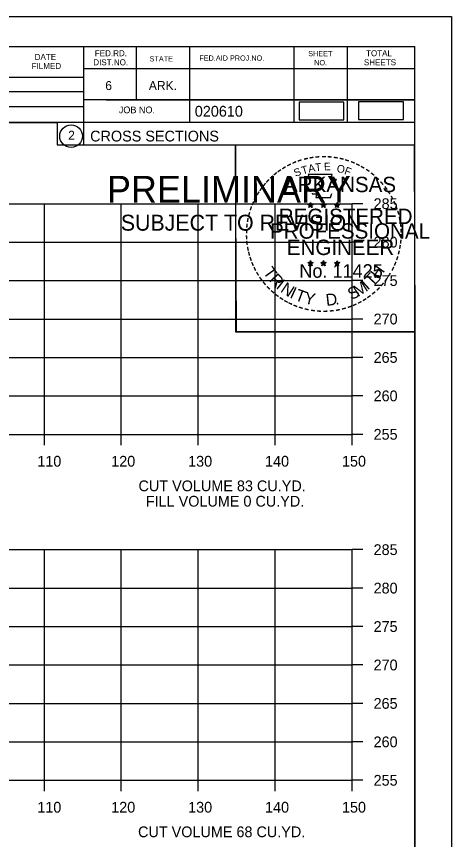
# Model space of a CAD drawing. Extents: x 1103485 to 1107180, y 2010593 to 2011873.
# Drawn here: x 1107123.6 to 1107180.1, y 2010699.1 to 2010806.2 of the extents above; entities that cross this region are included whole.
import ezdxf

# ---------------------------------------------------------------- set-up
doc = ezdxf.new("R2010")
doc.units = 0
for name, color, linetype in [('R_Axis', 7, 'Continuous'), ('R_Axis Annot', 7, 'Continuous'), ('R_Border', 7, 'Continuous'), ('R_Border PE', 7, 'Continuous'), ('R_Border Prem', 7, 'Continuous'), ('R_Grid', 7, 'Continuous'), ('R_No Plot', 7, 'Continuous'), ('R_Water', 7, 'Continuous')]:
    doc.layers.add(name, color=color, linetype=linetype)

msp = doc.modelspace()

# ---------------------------------------------------------------- linework, layer by layer
at = {"layer": 'R_Axis'}
for p, q in [((1107167.18, 2010751.82), (1107167.18, 2010781.82)), ((1107168.58, 2010781.82), (1107167.18, 2010781.82)), ((1107168.58, 2010776.82), (1107167.18, 2010776.82)), ((1107168.58, 2010771.82), (1107167.18, 2010771.82)), ((1107168.58, 2010766.82), (1107167.18, 2010766.82)), ((1107168.58, 2010761.82), (1107167.18, 2010761.82)), ((1107168.58, 2010756.82), (1107167.18, 2010756.82)), ((1106867.18, 2010751.82), (1107167.18, 2010751.82)), ((1107127.18, 2010750.42), (1107127.18, 2010751.82)), ((1107137.18, 2010750.42), (1107137.18, 2010751.82)), ((1107147.18, 2010750.42), (1107147.18, 2010751.82)), ((1107157.18, 2010750.42), (1107157.18, 2010751.82)), ((1107167.18, 2010750.42), (1107167.18, 2010751.82)), ((1107168.58, 2010751.82), (1107167.18, 2010751.82)), ((1107167.18, 2010706.82), (1107167.18, 2010736.82)), ((1107168.58, 2010736.82), (1107167.18, 2010736.82)), ((1107168.58, 2010731.82), (1107167.18, 2010731.82)), ((1107168.58, 2010726.82), (1107167.18, 2010726.82)), ((1107168.58, 2010721.82), (1107167.18, 2010721.82)), ((1107168.58, 2010716.82), (1107167.18, 2010716.82)), ((1107168.58, 2010711.82), (1107167.18, 2010711.82)), ((1106867.18, 2010706.82), (1107167.18, 2010706.82)), ((1107127.18, 2010705.42), (1107127.18, 2010706.82)), ((1107137.18, 2010705.42), (1107137.18, 2010706.82)), ((1107147.18, 2010705.42), (1107147.18, 2010706.82)), ((1107157.18, 2010705.42), (1107157.18, 2010706.82)), ((1107167.18, 2010705.42), (1107167.18, 2010706.82)), ((1107168.58, 2010706.82), (1107167.18, 2010706.82))]:
    msp.add_line(p, q, dxfattribs=at)
at = {"layer": 'R_Border'}
for p, q in [((1106859.18, 2010802.28), (1107175.36, 2010802.28)), ((1107132.26, 2010802.28), (1107132.26, 2010789.48)), ((1107139.1, 2010802.28), (1107139.1, 2010795.34)), ((1107146.04, 2010802.28), (1107146.04, 2010792.4)), ((1107159.62, 2010802.28), (1107159.62, 2010792.4)), ((1107166.56, 2010802.28), (1107166.56, 2010792.4)), ((1107175.36, 2010596.82), (1107175.36, 2010802.28)), ((1107175.36, 2010799.34), (1107132.26, 2010799.34)), ((1107175.36, 2010799.36), (1107175.36, 2010799.36)), ((1107093.1, 2010798.26), (1107132.26, 2010798.26)), ((1107093.1, 2010796.4), (1107132.26, 2010796.4)), ((1107175.36, 2010795.34), (1107132.26, 2010795.34)), ((1107135.22, 2010795.34), (1107175.36, 2010795.34)), ((1107093.1, 2010794.46), (1107132.26, 2010794.46)), ((1107175.36, 2010792.4), (1107093.1, 2010792.4)), ((1107132.26, 2010789.48), (1107175.36, 2010789.48))]:
    msp.add_line(p, q, dxfattribs=at)
msp.add_circle((1107130.65, 2010790.61), 1.47, dxfattribs=at)
at = {"layer": 'R_Border PE'}
for p, q in [((1107161.45, 2010781.73), (1107161.8, 2010781.62)), ((1107161.45, 2010781.73), (1107161.7, 2010781.69)), ((1107161.45, 2010781.73), (1107161.69, 2010781.61)), ((1107161.58, 2010781.32), (1107161.8, 2010781.62)), ((1107161.58, 2010781.32), (1107161.71, 2010781.57)), ((1107161.58, 2010781.32), (1107161.8, 2010781.54)), ((1107161.8, 2010781.99), (1107161.76, 2010781.73)), ((1107161.8, 2010781.62), (1107161.8, 2010781.99)), ((1107161.8, 2010781.99), (1107161.85, 2010781.74)), ((1107162.14, 2010781.73), (1107161.8, 2010781.62)), ((1107162.01, 2010781.32), (1107161.8, 2010781.62)), ((1107162.01, 2010781.32), (1107161.8, 2010781.54)), ((1107162.14, 2010781.73), (1107161.86, 2010781.68)), ((1107162.01, 2010781.32), (1107161.87, 2010781.61)), ((1107162.14, 2010781.73), (1107161.94, 2010781.63)), ((1107163.12, 2010781.73), (1107163.47, 2010781.62)), ((1107163.12, 2010781.73), (1107163.37, 2010781.69)), ((1107163.12, 2010781.73), (1107163.36, 2010781.61)), ((1107163.25, 2010781.32), (1107163.47, 2010781.62)), ((1107163.25, 2010781.32), (1107163.38, 2010781.57)), ((1107163.25, 2010781.32), (1107163.47, 2010781.54)), ((1107163.47, 2010781.99), (1107163.43, 2010781.73)), ((1107163.47, 2010781.62), (1107163.47, 2010781.99)), ((1107163.47, 2010781.99), (1107163.52, 2010781.74)), ((1107163.81, 2010781.73), (1107163.47, 2010781.62)), ((1107163.68, 2010781.32), (1107163.47, 2010781.62)), ((1107163.68, 2010781.32), (1107163.47, 2010781.54)), ((1107163.81, 2010781.73), (1107163.53, 2010781.68)), ((1107163.68, 2010781.32), (1107163.54, 2010781.61)), ((1107163.81, 2010781.73), (1107163.61, 2010781.63)), ((1107164.88, 2010781.72), (1107165.23, 2010781.61)), ((1107164.88, 2010781.72), (1107165.14, 2010781.67)), ((1107164.88, 2010781.72), (1107165.12, 2010781.6)), ((1107165.02, 2010781.31), (1107165.23, 2010781.61)), ((1107165.02, 2010781.31), (1107165.14, 2010781.56)), ((1107165.02, 2010781.31), (1107165.23, 2010781.53)), ((1107165.23, 2010781.97), (1107165.19, 2010781.72)), ((1107165.23, 2010781.61), (1107165.23, 2010781.97)), ((1107165.23, 2010781.97), (1107165.28, 2010781.72)), ((1107165.58, 2010781.72), (1107165.23, 2010781.61)), ((1107165.44, 2010781.31), (1107165.23, 2010781.61)), ((1107165.44, 2010781.31), (1107165.23, 2010781.53)), ((1107165.58, 2010781.72), (1107165.29, 2010781.67)), ((1107165.44, 2010781.31), (1107165.31, 2010781.6)), ((1107165.58, 2010781.72), (1107165.37, 2010781.62)), ((1107161.44, 2010774.16), (1107161.79, 2010774.05)), ((1107161.44, 2010774.16), (1107161.7, 2010774.11)), ((1107161.44, 2010774.16), (1107161.68, 2010774.04)), ((1107161.58, 2010773.75), (1107161.79, 2010774.05)), ((1107161.58, 2010773.75), (1107161.7, 2010773.99)), ((1107161.58, 2010773.75), (1107161.79, 2010773.97)), ((1107161.79, 2010774.41), (1107161.75, 2010774.16)), ((1107161.79, 2010774.05), (1107161.79, 2010774.41)), ((1107161.79, 2010774.41), (1107161.84, 2010774.16)), ((1107162.14, 2010774.16), (1107161.79, 2010774.05)), ((1107162.01, 2010773.75), (1107161.79, 2010774.05)), ((1107162.01, 2010773.75), (1107161.79, 2010773.96)), ((1107162.14, 2010774.16), (1107161.85, 2010774.11)), ((1107162.01, 2010773.75), (1107161.87, 2010774.04)), ((1107162.14, 2010774.16), (1107161.94, 2010774.06)), ((1107163.11, 2010774.16), (1107163.46, 2010774.05)), ((1107163.11, 2010774.16), (1107163.37, 2010774.11)), ((1107163.11, 2010774.16), (1107163.35, 2010774.04)), ((1107163.25, 2010773.75), (1107163.46, 2010774.05)), ((1107163.25, 2010773.75), (1107163.37, 2010773.99)), ((1107163.25, 2010773.75), (1107163.46, 2010773.97)), ((1107163.46, 2010774.41), (1107163.42, 2010774.16)), ((1107163.46, 2010774.05), (1107163.46, 2010774.41)), ((1107163.46, 2010774.41), (1107163.51, 2010774.16)), ((1107163.81, 2010774.16), (1107163.46, 2010774.05)), ((1107163.68, 2010773.75), (1107163.46, 2010774.05)), ((1107163.68, 2010773.75), (1107163.46, 2010773.96)), ((1107163.81, 2010774.16), (1107163.52, 2010774.11)), ((1107163.68, 2010773.75), (1107163.54, 2010774.04)), ((1107163.81, 2010774.16), (1107163.61, 2010774.06)), ((1107164.88, 2010774.15), (1107165.23, 2010774.04)), ((1107164.88, 2010774.15), (1107165.13, 2010774.1)), ((1107164.88, 2010774.15), (1107165.12, 2010774.03)), ((1107165.01, 2010773.74), (1107165.23, 2010774.04)), ((1107165.01, 2010773.74), (1107165.14, 2010773.98)), ((1107165.01, 2010773.74), (1107165.23, 2010773.96)), ((1107165.23, 2010774.4), (1107165.19, 2010774.15)), ((1107165.23, 2010774.04), (1107165.23, 2010774.4)), ((1107165.23, 2010774.4), (1107165.28, 2010774.15)), ((1107165.58, 2010774.15), (1107165.23, 2010774.04)), ((1107165.44, 2010773.74), (1107165.23, 2010774.04)), ((1107165.44, 2010773.74), (1107165.23, 2010773.95)), ((1107165.58, 2010774.15), (1107165.29, 2010774.1)), ((1107165.44, 2010773.74), (1107165.31, 2010774.03)), ((1107165.58, 2010774.15), (1107165.37, 2010774.05))]:
    msp.add_line(p, q, dxfattribs=at)
for points in [[(1107161.49, 2010785.61), (1107161.76, 2010784.78)], [(1107165, 2010784.69), (1107165.14, 2010784.97), (1107164.46, 2010784.95), (1107164.61, 2010785.61), (1107161.49, 2010785.61)], [(1107161.98, 2010783.19), (1107161.98, 2010783.1), (1107162.54, 2010783.08), (1107162.49, 2010782.61), (1107164.36, 2010782.61), (1107164.56, 2010783.14)], [(1107161.8, 2010781.99), (1107162.01, 2010781.32), (1107161.45, 2010781.73), (1107162.14, 2010781.73), (1107161.58, 2010781.32), (1107161.8, 2010781.99)], [(1107163.47, 2010781.99), (1107163.68, 2010781.32), (1107163.12, 2010781.73), (1107163.81, 2010781.73), (1107163.25, 2010781.32), (1107163.47, 2010781.99)], [(1107165.23, 2010781.97), (1107165.44, 2010781.31), (1107164.88, 2010781.72), (1107165.58, 2010781.72), (1107165.02, 2010781.31), (1107165.23, 2010781.97)], [(1107161.79, 2010774.41), (1107162.01, 2010773.75), (1107161.44, 2010774.16), (1107162.14, 2010774.16), (1107161.58, 2010773.75), (1107161.79, 2010774.41)], [(1107163.46, 2010774.41), (1107163.68, 2010773.75), (1107163.11, 2010774.16), (1107163.81, 2010774.16), (1107163.25, 2010773.75), (1107163.46, 2010774.41)], [(1107165.23, 2010774.4), (1107165.44, 2010773.74), (1107164.88, 2010774.15), (1107165.58, 2010774.15), (1107165.01, 2010773.74), (1107165.23, 2010774.4)]]:
    msp.add_lwpolyline(points, dxfattribs=at)
for centre, radius in [((1107161.8, 2010781.62), 0.172), ((1107161.8, 2010781.62), 0.145), ((1107161.8, 2010781.62), 0.116), ((1107161.8, 2010781.62), 0.0991), ((1107161.8, 2010781.62), 0.0747), ((1107161.8, 2010781.62), 0.0495), ((1107161.8, 2010781.62), 0.0296), ((1107163.47, 2010781.62), 0.172), ((1107163.47, 2010781.62), 0.145), ((1107163.47, 2010781.62), 0.116), ((1107163.47, 2010781.62), 0.0991), ((1107163.47, 2010781.62), 0.0747), ((1107163.47, 2010781.62), 0.0495), ((1107163.47, 2010781.62), 0.0296), ((1107165.23, 2010781.61), 0.172), ((1107165.23, 2010781.61), 0.145), ((1107165.23, 2010781.61), 0.116), ((1107165.23, 2010781.61), 0.0991), ((1107165.23, 2010781.61), 0.0747), ((1107165.23, 2010781.61), 0.0495), ((1107165.23, 2010781.61), 0.0296), ((1107161.79, 2010774.05), 0.172), ((1107161.79, 2010774.05), 0.145), ((1107161.79, 2010774.05), 0.116), ((1107161.79, 2010774.05), 0.0991), ((1107161.79, 2010774.05), 0.0747), ((1107161.79, 2010774.05), 0.0495), ((1107161.79, 2010774.05), 0.0296), ((1107163.46, 2010774.05), 0.172), ((1107163.46, 2010774.05), 0.145), ((1107163.46, 2010774.05), 0.116), ((1107163.46, 2010774.05), 0.0991), ((1107163.46, 2010774.05), 0.0747), ((1107163.46, 2010774.05), 0.0495), ((1107163.46, 2010774.05), 0.0296), ((1107165.23, 2010774.04), 0.172), ((1107165.23, 2010774.04), 0.145), ((1107165.23, 2010774.04), 0.116), ((1107165.23, 2010774.04), 0.0991), ((1107165.23, 2010774.04), 0.0747), ((1107165.23, 2010774.04), 0.0495), ((1107165.23, 2010774.04), 0.0296)]:
    msp.add_circle(centre, radius, dxfattribs=at)
at = {"layer": 'R_Grid'}
for p, q in [((1106867.18, 2010781.82), (1107167.18, 2010781.82)), ((1107127.18, 2010751.82), (1107127.18, 2010781.82)), ((1107137.18, 2010751.82), (1107137.18, 2010781.82)), ((1107147.18, 2010751.82), (1107147.18, 2010781.82)), ((1107157.18, 2010751.82), (1107157.18, 2010781.82)), ((1107167.18, 2010751.82), (1107167.18, 2010781.82)), ((1106867.18, 2010776.82), (1107167.18, 2010776.82)), ((1106867.18, 2010771.82), (1107167.18, 2010771.82)), ((1106867.18, 2010766.82), (1107167.18, 2010766.82)), ((1106867.18, 2010761.82), (1107167.18, 2010761.82)), ((1106867.18, 2010756.82), (1107167.18, 2010756.82)), ((1106867.18, 2010751.82), (1107167.18, 2010751.82)), ((1106867.18, 2010736.82), (1107167.18, 2010736.82)), ((1107127.18, 2010706.82), (1107127.18, 2010736.82)), ((1107137.18, 2010706.82), (1107137.18, 2010736.82)), ((1107147.18, 2010706.82), (1107147.18, 2010736.82)), ((1107157.18, 2010706.82), (1107157.18, 2010736.82)), ((1107167.18, 2010706.82), (1107167.18, 2010736.82)), ((1106867.18, 2010731.82), (1107167.18, 2010731.82)), ((1106867.18, 2010726.82), (1107167.18, 2010726.82)), ((1106867.18, 2010721.82), (1107167.18, 2010721.82)), ((1106867.18, 2010716.82), (1107167.18, 2010716.82)), ((1106867.18, 2010711.82), (1107167.18, 2010711.82)), ((1106867.18, 2010706.82), (1107167.18, 2010706.82))]:
    msp.add_line(p, q, dxfattribs=at)
at = {"layer": 'R_No Plot'}
for p, q in [((1106846.78, 2010806.17), (1107180.12, 2010806.17)), ((1107151.4, 2010767.02), (1107151.4, 2010767.02))]:
    msp.add_line(p, q, dxfattribs=at)
for points in [[(1106846.78, 2010806.17), (1107180.12, 2010806.17), (1107180.12, 2010592.83), (1106846.78, 2010592.83)], [(1107093.1, 2010802.28), (1107093.1, 2010792.4), (1107128.84, 2010792.4), (1107128.84, 2010789.48), (1107152.04, 2010789.48), (1107152.04, 2010765.14), (1107175.36, 2010765.14), (1107175.36, 2010596.82), (1106859.18, 2010596.82), (1106859.18, 2010802.28)], [(1107152.04, 2010789.48), (1107175.24, 2010789.48), (1107175.36, 2010765.14), (1107152.16, 2010765.14)]]:
    msp.add_lwpolyline(points, close=True, dxfattribs=at)
at = {"layer": 'R_Water'}
for points in [[(1107160.3, 2010792.73), (1107166.13, 2010792.73), (1107166.13, 2010795.04), (1107160.3, 2010795.04)], [(1107168.04, 2010792.77), (1107173.87, 2010792.77), (1107173.87, 2010795.08), (1107168.04, 2010795.08)]]:
    msp.add_lwpolyline(points, close=True, dxfattribs=at)

# ---------------------------------------------------------------- texts
at = {"layer": 'R_Axis Annot'}
for s, p in [('285', (1107169.98, 2010781.12)), ('280', (1107169.98, 2010776.12)), ('275', (1107169.98, 2010771.12)), ('270', (1107169.98, 2010766.12)), ('265', (1107169.98, 2010761.12)), ('260', (1107169.98, 2010756.12)), ('255', (1107169.98, 2010751.12)), ('110', (1107126.26, 2010747.62)), ('120', (1107135.87, 2010747.62)), ('130', (1107145.87, 2010747.62)), ('140', (1107155.87, 2010747.62)), ('150', (1107165.87, 2010747.62)), ('CUT VOLUME 83 CU.YD.', (1107139.42, 2010744.42)), ('FILL VOLUME 0 CU.YD.', (1107140.37, 2010742.42)), ('285', (1107169.98, 2010736.12)), ('280', (1107169.98, 2010731.12)), ('275', (1107169.98, 2010726.12)), ('270', (1107169.98, 2010721.12)), ('265', (1107169.98, 2010716.12)), ('260', (1107169.98, 2010711.12)), ('255', (1107169.98, 2010706.12)), ('110', (1107126.26, 2010702.62)), ('120', (1107135.87, 2010702.62)), ('130', (1107145.87, 2010702.62)), ('140', (1107155.87, 2010702.62)), ('150', (1107165.87, 2010702.62)), ('CUT VOLUME 68 CU.YD.', (1107139.36, 2010699.42))]:
    msp.add_text(s, height=1.4, dxfattribs=at).set_placement(p)
at = {"layer": 'R_Border'}
for s, height, p in [('FED.RD.', 0.782, (1107133.74, 2010801)), ('SHEET', 0.684, (1107161.48, 2010801)), ('TOTAL', 0.782, (1107169, 2010801)), ('DATE', 0.782, (1107125.92, 2010800.52)), ('DIST.NO.', 0.782, (1107133.54, 2010799.82)), ('STATE', 0.684, (1107140.86, 2010800.32)), ('FED.AID PROJ.NO.', 0.684, (1107147.32, 2010800.42)), ('NO.', 0.684, (1107162.26, 2010799.82)), ('SHEETS', 0.782, (1107168.72, 2010799.82)), ('FILMED', 0.782, (1107125.52, 2010799.34)), ('6', 1.17, (1107135.1, 2010796.6)), ('ARK.', 1.172, (1107140.76, 2010796.6)), ('JOB NO.', 0.879, (1107136.86, 2010793.58)), ('020610', 1.4, (1107146.74, 2010793.14)), ('2', 1.17, (1107130.27, 2010790.13)), ('CROSS SECTIONS', 1.4, (1107133.13, 2010789.91))]:
    msp.add_text(s, height=height, rotation=360, dxfattribs=at).set_placement(p)
at = {"layer": 'R_Border PE'}
for s, height, rotation, p in [('-', 1.6, 13.6301, (1107160.99, 2010786.98)), ('-', 1.6, 10.2193, (1107161.67, 2010787.14)), ('-', 1.6, 5.8968, (1107162.39, 2010787.25)), ('-', 1.6, 0.1862, (1107163.17, 2010787.32)), ('-', 1.6, 357.743, (1107163.89, 2010787.31)), ('-', 1.6, 352.1617, (1107164.63, 2010787.25)), ('-', 1.6, 347.2049, (1107165.35, 2010787.14)), ('-', 1.6, 342.3362, (1107165.99, 2010786.98)), ('-', 1.6, 34.0636, (1107158.37, 2010785.78)), ('-', 1.6, 28.7918, (1107158.97, 2010786.15)), ('-', 1.6, 24.3072, (1107159.6, 2010786.47)), ('-', 1.6, 19.1761, (1107160.24, 2010786.74)), ('T', 1, 16.4036, (1107160.76, 2010785.62)), ('A', 1, 11.2132, (1107161.58, 2010785.87)), ('T', 1, 6.0228, (1107162.43, 2010786.04)), ('E', 1, 0.8323, (1107163.54, 2010786.15)), ('O', 1, 350.4515, (1107165.14, 2010785.94)), ('F', 1, 340.0707, (1107166.1, 2010785.71)), ('-', 1.6, 337.8551, (1107166.72, 2010786.76)), ('-', 1.6, 334.1211, (1107167.35, 2010786.49)), ('-', 1.6, 329.6409, (1107167.93, 2010786.21)), ('-', 1.6, 42.9622, (1107156.89, 2010784.59)), ('-', 1.6, 38.9507, (1107157.32, 2010785.01)), ('-', 1.6, 36.2317, (1107157.8, 2010785.39)), ('S', 1, 21.594, (1107159.84, 2010785.29)), ('-', 1.6, 325.8627, (1107168.58, 2010785.85)), ('-', 1.6, 320.5297, (1107169.19, 2010785.42)), ('-', 1.6, 50.6142, (1107156.04, 2010783.63)), ('-', 1.6, 48.423, (1107156.44, 2010784.11)), ('ARKANSAS', 2, 360, (1107158.34, 2010783.32)), ('-', 1.6, 315.5786, (1107169.78, 2010784.93)), ('-', 1.6, 309.8797, (1107170.35, 2010784.38)), ('-', 1.6, 58.0706, (1107155.3, 2010782.53)), ('-', 1.6, 54.2325, (1107155.62, 2010783.06)), ('-', 1.6, 306.6522, (1107170.88, 2010783.78)), ('-', 1.4, 303.6753, (1107171.36, 2010783.21)), ('-', 1.6, 62.8713, (1107154.98, 2010781.92)), ('-', 1.6, 299.6684, (1107171.68, 2010782.6)), ('-', 1.6, 72.3945, (1107154.51, 2010780.68)), ('-', 1.6, 67.7743, (1107154.73, 2010781.31)), ('REGISTERED', 2, 360, (1107157.66, 2010779.17)), ('DWB', 0.01, 360, (1107161.78, 2010781.62)), ('DWB', 0.01, 360, (1107163.45, 2010781.62)), ('DWB', 0.01, 360, (1107165.22, 2010781.6)), ('-', 1.6, 294.6628, (1107172.01, 2010781.99)), ('-', 1.6, 290.5728, (1107172.26, 2010781.42)), ('-', 1.6, 75.461, (1107154.31, 2010779.96)), ('-', 1.6, 285.1233, (1107172.5, 2010780.84)), ('-', 1.6, 280.5493, (1107172.7, 2010780.09)), ('-', 1.6, 85.1863, (1107154.1, 2010778.56)), ('-', 1.6, 81.2013, (1107154.18, 2010779.25)), ('PROFESSIONAL', 2, 360, (1107156.52, 2010777.27)), ('-', 1.6, 276.5962, (1107172.86, 2010779.33)), ('-', 1.6, 89.0622, (1107154.08, 2010777.86)), ('-', 1.6, 274.3301, (1107172.92, 2010778.6)), ('-', 1.6, 94.1959, (1107154.11, 2010777.13)), ('-', 1.6, 98.9479, (1107154.18, 2010776.47)), ('ENGINEER', 2, 360, (1107158.7, 2010775.14)), ('-', 1.6, 263.5172, (1107172.94, 2010777.31)), ('-', 1.6, 269.9407, (1107172.95, 2010777.97)), ('-', 1.6, 101.7149, (1107154.32, 2010775.73)), ('-', 1.6, 260.9953, (1107172.86, 2010776.65)), ('-', 1.6, 105.4578, (1107154.48, 2010775.14)), ('-', 1.6, 109.0874, (1107154.7, 2010774.51)), ('-', 1.6, 252.8681, (1107172.57, 2010775.25)), ('-', 1.6, 255.7626, (1107172.75, 2010775.97)), ('-', 1.6, 114.0643, (1107154.95, 2010773.91)), ('T', 1.54, 306.0406, (1107155.55, 2010772.89)), ('No. 11425', 1.757, 360, (1107160.33, 2010772.19)), ('DWB', 0.01, 360, (1107161.78, 2010774.04)), ('DWB', 0.01, 360, (1107163.45, 2010774.04)), ('DWB', 0.01, 360, (1107165.22, 2010774.03)), ('H', 1.54, 54.6088, (1107170.67, 2010771.92)), ('-', 1.6, 247.8887, (1107172.35, 2010774.58)), ('-', 1.6, 115.7289, (1107155.25, 2010773.29)), ('-', 1.6, 120.4471, (1107155.61, 2010772.71)), ('R', 1.54, 314.005, (1107156.32, 2010771.84)), ('T', 1.54, 46.6444, (1107169.78, 2010770.98)), ('-', 1.6, 239.0712, (1107171.69, 2010773.2)), ('-', 1.6, 244.6197, (1107172.09, 2010773.95)), ('-', 1.6, 125.8934, (1107156.01, 2010772.15)), ('-', 1.6, 130.7181, (1107156.48, 2010771.59)), ('I', 1.54, 321.9694, (1107157.22, 2010770.91)), ('N', 1.54, 326.5002, (1107157.78, 2010770.43)), ('M', 1.54, 32.6563, (1107167.94, 2010769.65)), ('I', 1.54, 42.1136, (1107169.22, 2010770.5)), ('-', 1.6, 231.2538, (1107170.86, 2010771.98)), ('-', 1.6, 233.8452, (1107171.29, 2010772.55)), ('-', 1.6, 134.2238, (1107156.99, 2010771.05)), ('-', 1.6, 138.9338, (1107157.52, 2010770.59)), ('I', 1.54, 335.3603, (1107158.99, 2010769.65)), ('T', 1.54, 339.8912, (1107159.65, 2010769.32)), ('S', 1.54, 26.9312, (1107167.1, 2010769.25)), ('-', 1.6, 225.7653, (1107170.38, 2010771.42)), ('-', 1.6, 144.6463, (1107158.07, 2010770.18)), ('-', 1.6, 148.0898, (1107158.64, 2010769.81)), ('Y', 1.54, 347.8556, (1107160.87, 2010768.88)), ('D', 1.54, 6.3969, (1107163.85, 2010768.52)), ('-', 1.6, 212.2491, (1107168.78, 2010770.05)), ('-', 1.6, 215.7363, (1107169.31, 2010770.44)), ('-', 1.6, 221.0851, (1107169.86, 2010770.91)), ('-', 1.6, 151.5704, (1107159.21, 2010769.48)), ('-', 1.6, 154.6002, (1107159.74, 2010769.24)), ('-', 1.6, 158.5612, (1107160.36, 2010768.98)), ('-', 1.6, 162.7983, (1107161.05, 2010768.77)), ('.', 1.54, 13.7642, (1107165.05, 2010768.64)), ('-', 1.6, 200.7184, (1107166.98, 2010769.11)), ('-', 1.6, 204.2516, (1107167.6, 2010769.38)), ('-', 1.6, 207.3568, (1107168.22, 2010769.7)), ('-', 1.6, 167.5555, (1107161.76, 2010768.61)), ('-', 1.6, 173.1155, (1107162.53, 2010768.5)), ('-', 1.6, 176.5183, (1107163.28, 2010768.44)), ('-', 1.6, 181.5918, (1107164.03, 2010768.46)), ('-', 1.6, 185.8167, (1107164.84, 2010768.54)), ('-', 1.6, 191.2858, (1107165.57, 2010768.67)), ('-', 1.6, 195.4743, (1107166.3, 2010768.87))]:
    msp.add_text(s, height=height, rotation=rotation, dxfattribs=at).set_placement(p)
at = {"layer": 'R_Border Prem'}
for s, height, p in [('PRELIMINARY', 3.5, (1107135.31, 2010781.94)), ('DWB', 0.01, (1107136.06, 2010783.79)), ('SUBJECT TO REVISION', 2.0751, (1107137.12, 2010778.31))]:
    msp.add_text(s, height=height, rotation=360, dxfattribs=at).set_placement(p)

doc.saveas('drawing.dxf')
